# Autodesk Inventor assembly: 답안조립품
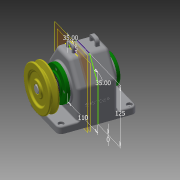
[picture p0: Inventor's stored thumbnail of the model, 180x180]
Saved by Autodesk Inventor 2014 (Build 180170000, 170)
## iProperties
Created: 2016-12
Part Number: 답안조립품
Document SubType Name: Assembly
Designer: user
Author: user
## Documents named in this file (15)
- C:\Users\user\Desktop\461208V1001\답안조립품.iam
- C:\Users\user\Desktop\461208V1001\본체.ipt
- C:\Users\user\Desktop\461208V1001\뒤커버.ipt
- C:\Users\user\Desktop\461208V1001\앞커버.ipt
- C:\Users\user\Desktop\461208V1001\축.ipt
- C:\Users\user\Desktop\461208V1001\베어링 6203.ipt
- C:\Users\user\Desktop\461208V1001\키 - 6 x 6 x 22.ipt
- C:\Users\user\Desktop\461208V1001\키 - 5 x 5 x 18.ipt
- C:\Users\user\Desktop\461208V1001\스퍼기어.ipt
- C:\Users\user\Desktop\461208V1001\오일씰 28 40 8.ipt
- C:\Users\user\Desktop\461208V1001\V-벨트풀리.ipt
- C:\Users\user\Desktop\461208V1001\멈춤나사 - M4x10.ipt
- C:\Users\user\Desktop\461208V1001\볼트 M3 x 8.ipt
- C:\Users\user\Desktop\461208V1001\볼트 M3 x 10.ipt
- C:\Users\user\Desktop\461208V1001\부시.ipt
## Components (9 placed, 3 different names)
1. V-벨트풀리:1 — Mate:25, Mate:26
2. ISO 4762 M3 x 8:1 — Mate:29, Mate:30
3. ISO 4762 M3 x 8:2
4. ISO 4762 M3 x 8:3
5. ISO 4762 M3 x 8:4
6. ISO 4762 M3 x 10:1 — Mate:31, Mate:32
7. ISO 4762 M3 x 10:2
8. ISO 4762 M3 x 10:3
9. ISO 4762 M3 x 10:4
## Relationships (6: Mate 6)
- Mate:25: V-벨트풀리:1
- Mate:26: V-벨트풀리:1
- Mate:29: ISO 4762 M3 x 8:1
- Mate:30: ISO 4762 M3 x 8:1
- Mate:31: ISO 4762 M3 x 10:1
- Mate:32: ISO 4762 M3 x 10:1
